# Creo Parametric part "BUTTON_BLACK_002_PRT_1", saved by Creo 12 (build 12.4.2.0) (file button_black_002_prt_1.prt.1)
Units: Custom; MM, KILOGRAM, SECS

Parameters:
  PTC_WM_ITERATION = "0"
  PTC_WM_VERSION = "-.0"
  PTC_WM_LIFECYCLE_STATE = "In Work"
  PTC_WM_LIFECYCLE = "MO_CADDocument"
  PTC_WM_CREATED_BY = "Maximilian Roepper (Z0017RMS: MO)"
  PTC_WM_CREATED_ON = "18-Sep-26 11:36:42 AM"
  PTC_WM_MODIFIED_BY = "Maximilian Roepper (Z0017RMS: MO)"
  PTC_WM_MODIFIED_ON = "18-Sep-26 11:36:46 AM"
  PDMLINKNUMBER = "PDM000071455007"
  PTC_WM_NAME = "button_black_002_prt_1.prt"
  PTC_WM_NUMBER = "PDM000071455007"

Other parameters: WEIGHT, WEIGHT_FACTOR, WEIGHT_ADD, _MASS_TEMP, _DIFF_TEMP, MC_ERRORS, SUPPLIER

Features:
  1. coordinate system
  2. datum plane "PRT_YZ"
  3. datum plane "PRT_XY"
  4. datum plane "PRT_XZ"
  5. coordinate system
  6. datum axis
  7. datum axis
  8. datum axis
  9. coordinate system
  10. imported feature
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
Other named items: PRT, SIEMENS_MO, DRW_VIEW_ORG, PRT_X, PRT_Y, PRT_Z, CS0, ROUGH_GROB

Layers: 00_STD_CSYS-KSYS, 01_STD_PLANES-EBENEN, 02_STD_AXES-ACHSEN, 03_STD_CSYS-KSYS, 24_IMPORT_FEAT-IMPORT_KE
